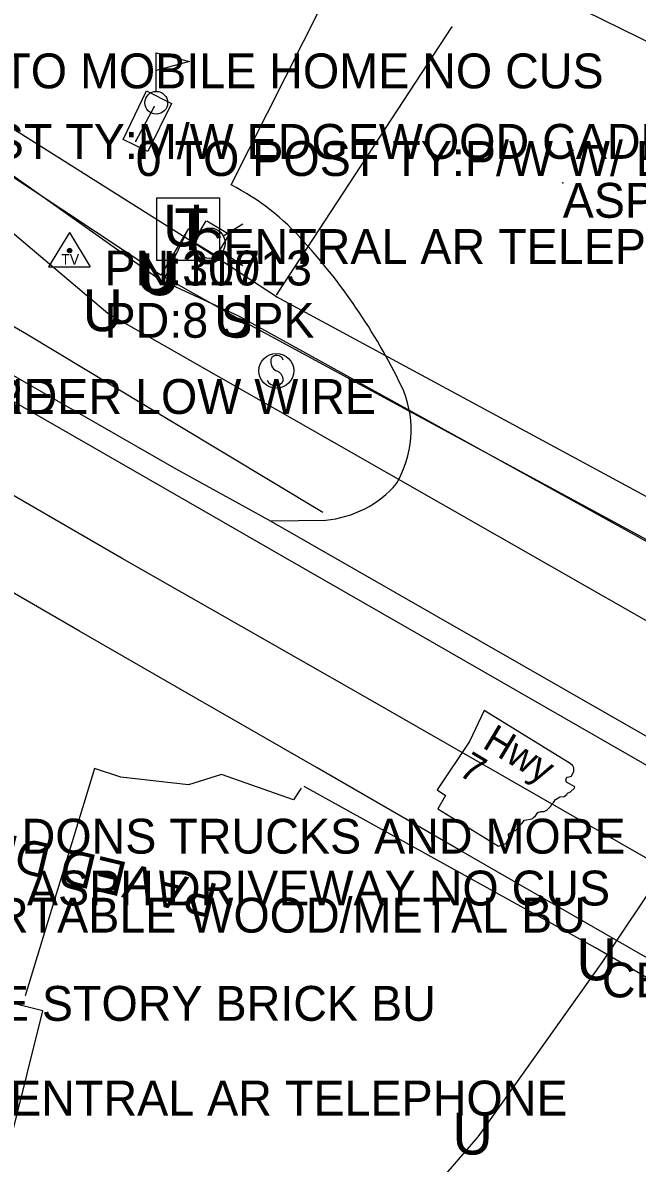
# Model space of a CAD drawing. Extents: x 954793 to 988390, y 1867850 to 1924428.
# Drawn here: x 967016.2 to 967104.3, y 1897074.8 to 1897238.3 of the extents above; entities that cross this region are included whole.
import ezdxf

# ---------------------------------------------------------------- set-up
doc = ezdxf.new("R2010")
doc.units = 0
for name, color, linetype in [('Default', 7, 'Continuous'), ('S_BUILDING', 7, 'Continuous'), ('S_DITCHLINE', 7, 'Continuous'), ('S_DRIVEWAY', 7, 'Continuous'), ('S_DRIVEWAY_ANNOT', 7, 'Continuous'), ('S_EDGE_CONCRETE', 7, 'Continuous'), ('S_EDGE_PAVEMENT', 7, 'Continuous'), ('S_ELECTRIC_UTILITIES_ANNOT', 7, 'Continuous'), ('S_FENCE', 7, 'Continuous'), ('S_FIBER_OPTIC_CABLE', 7, 'Continuous'), ('S_FLAG_POLE', 7, 'Continuous'), ('S_HWY_SYMBOLS', 7, 'Continuous'), ('S_MISC_TOPO_POINT', 7, 'Continuous'), ('S_MSC_PT_SYM', 7, 'Continuous'), ('S_PARKING', 7, 'Continuous'), ('S_PAVEMENT_CROWN', 7, 'Continuous'), ('S_SECONDARY_CTL', 7, 'Continuous'), ('S_SECONDARY_CTL_ANNOT', 7, 'Continuous'), ('S_SHOULDER', 7, 'Continuous'), ('S_SIGN', 7, 'Continuous'), ('S_SIGN_ANNOT', 7, 'Continuous'), ('S_SURVEY_TEXT_ANNOT', 7, 'Continuous'), ('S_TELEPHONE_UTILITIES', 7, 'Continuous'), ('S_TELEPHONE_UTILITIES_ANNOT', 7, 'Continuous'), ('S_UNDERGROUND_CABLE', 7, 'Continuous'), ('S_UNDERGROUND_CABLE_ANNOT', 7, 'Continuous'), ('S_UTL_PT_SYM', 7, 'Continuous'), ('S_WATER_UTILITIES', 7, 'Continuous')]:
    doc.layers.add(name, color=color, linetype=linetype)

msp = doc.modelspace()

# ---------------------------------------------------------------- linework, layer by layer
at = {"layer": 'S_BUILDING'}
for points in [[(967065.51, 1897255.42), (967081.45, 1897287.84), (967122.87, 1897267.47), (967129.83, 1897281.63), (967155.34, 1897269.09), (967148.3, 1897254.77), (967180.37, 1897239), (967164.5, 1897206.74)], [(967019.08, 1897096.61), (966964.64, 1897110.21), (966957.91, 1897083.3), (967012.36, 1897069.7)]]:
    msp.add_lwpolyline(points, close=True, dxfattribs=at)
at = {"layer": 'S_DITCHLINE'}
msp.add_lwpolyline([(967059.25, 1897168.09), (967038.01, 1897180.86), (967016.77, 1897193.64), (966999.71, 1897203.61), (966982.65, 1897213.58)], dxfattribs=at)
at = {"layer": 'S_DRIVEWAY'}
msp.add_lwpolyline([(967056.12, 1897128.53), (967055.04, 1897126.89), (967044.72, 1897130.5), (967039.98, 1897129.01), (967030.26, 1897130.1), (967026.52, 1897131.35), (967021.55, 1897115.05), (967016.59, 1897098.75)], dxfattribs=at)
at = {"layer": 'S_EDGE_CONCRETE'}
msp.add_lwpolyline([(967030.61, 1897221.59), (967033.97, 1897228.53), (967037.54, 1897226.74), (967034.14, 1897219.87)], close=True, dxfattribs=at)
at = {"layer": 'S_EDGE_PAVEMENT'}
for points in [[(967224.91, 1897063.58), (967209.92, 1897072.14), (967194.93, 1897080.7), (967179.94, 1897089.26), (967164.94, 1897097.82), (967149.95, 1897106.38), (967130.9, 1897117.31), (967111.86, 1897128.24), (967091.31, 1897140.05), (967070.75, 1897151.86), (967053.62, 1897161.71), (967036.49, 1897171.56), (967019.54, 1897181.3), (967002.59, 1897191.04), (966985.41, 1897201.15), (966968.24, 1897211.26), (966949.08, 1897223.02), (966929.92, 1897234.79), (966913.05, 1897245.66), (966896.19, 1897256.54), (966878.48, 1897268.84), (966872.08, 1897273.28)], [(967228.06, 1897034.22), (967213.07, 1897042.79), (967198.07, 1897051.35), (967183.07, 1897059.92), (967168.07, 1897068.49), (967153.07, 1897077.06), (967138.08, 1897085.63), (967118.85, 1897096.66), (967099.63, 1897107.69), (967079.02, 1897119.57), (967058.4, 1897131.45), (967041.37, 1897141.26), (967024.35, 1897151.07), (967007.47, 1897160.83), (966990.59, 1897170.6), (966973.37, 1897180.77), (966956.14, 1897190.94), (966936.51, 1897202.73), (966916.87, 1897214.51), (966899.69, 1897225.68), (966882.51, 1897236.85), (966864.51, 1897249.13)]]:
    msp.add_lwpolyline(points, dxfattribs=at)
at = {"layer": 'S_FENCE'}
msp.add_lwpolyline([(967042.6, 1897209.93), (967045.82, 1897208), (967043.93, 1897204.89), (967040.72, 1897206.84), (967042.49, 1897209.89)], dxfattribs=at)
at = {"layer": 'S_FIBER_OPTIC_CABLE'}
for p, q in [((967035.71, 1897201.53), (967003.19, 1897224.63)), ((967047.27, 1897196.19), (967035.71, 1897201.53)), ((967126.15, 1897152.57), (967047.27, 1897196.19))]:
    msp.add_line(p, q, dxfattribs=at)
at = {"layer": 'S_FLAG_POLE'}
for p, q in [((967035.36, 1897228.48), (967035.36, 1897234.02)), ((967035.36, 1897234.02), (967040.12, 1897232.74)), ((967040.12, 1897232.74), (967035.36, 1897231.47))]:
    msp.add_line(p, q, dxfattribs=at)
msp.add_circle((967035.36, 1897226.85), 1.63, dxfattribs=at)
at = {"layer": 'S_HWY_SYMBOLS'}
msp.add_lwpolyline([(967082.36, 1897139.67), (967080.26, 1897135.22), (967075.61, 1897128.32), (967076.8, 1897127.5), (967075.74, 1897125.57), (967084.41, 1897120.25), (967085.5, 1897120.59), (967085.91, 1897121.43), (967085.84, 1897121.97), (967086.45, 1897122.49), (967086.83, 1897122.46), (967087.12, 1897122.78), (967087.29, 1897123.07), (967087.75, 1897123.49), (967088.12, 1897123.96), (967089.24, 1897124.17), (967089.45, 1897124.35), (967089.7, 1897124.6), (967090.07, 1897125.06), (967090.54, 1897125.18), (967090.96, 1897125.22), (967091.35, 1897125.38), (967091.6, 1897125.63), (967091.89, 1897125.94), (967092.07, 1897126.23), (967092.32, 1897126.48), (967092.58, 1897126.92), (967092.69, 1897126.95), (967093.06, 1897127.22), (967093.22, 1897127.32), (967093.83, 1897127.35), (967094.19, 1897127.63), (967094.32, 1897127.85), (967094.72, 1897128.01), (967095.33, 1897128.53), (967095.34, 1897128.72), (967094.18, 1897129.42), (967094.05, 1897129.69), (967094.2, 1897130.1), (967094.54, 1897130.19), (967094.89, 1897130.27), (967095.21, 1897130.97), (967095.22, 1897131.47), (967095.08, 1897131.74), (967094.69, 1897132.08), (967082.36, 1897139.67)], dxfattribs=at)
at = {"layer": 'S_MSC_PT_SYM'}
for points in [[(967035.04, 1897226.28), (967035.04, 1897226.33), (967035.04, 1897226.28), (967034.99, 1897226.28), (967035.04, 1897226.28), (967035.04, 1897226.23), (967035.04, 1897226.28), (967035.09, 1897226.28)], [(967032.41, 1897221.34), (967032.41, 1897221.39), (967032.41, 1897221.34), (967032.36, 1897221.34), (967032.41, 1897221.34), (967032.41, 1897221.29), (967032.41, 1897221.34), (967032.46, 1897221.34)], [(967093.62, 1897215.35), (967093.62, 1897215.4), (967093.62, 1897215.35), (967093.57, 1897215.35), (967093.62, 1897215.35), (967093.62, 1897215.3), (967093.62, 1897215.35), (967093.67, 1897215.35)], [(967016.82, 1897116.72), (967016.82, 1897116.77), (967016.82, 1897116.72), (967016.77, 1897116.72), (967016.82, 1897116.72), (967016.82, 1897116.67), (967016.82, 1897116.72), (967016.87, 1897116.72)]]:
    msp.add_lwpolyline(points, dxfattribs=at)
at = {"layer": 'S_PARKING'}
for points in [[(967046.08, 1897215.07), (967064.23, 1897251.14), (967082.58, 1897241.92), (967086.54, 1897249.56)], [(967051.83, 1897166.87), (967059.66, 1897166.99)]]:
    msp.add_lwpolyline(points, dxfattribs=at)
for centre, major_axis, ratio, start_param, end_param in [((967030.19, 1897184.38), (-34.3, 6.15), 0.990938, 4.031216, 4.414458), ((966993.04, 1897148.79), (26.98, 81.77), 0.998092, 5.470715, 5.771687), ((967056.82, 1897179.88), (7.86, 12.92), 0.99535, 4.725896, 5.636188), ((967058.37, 1897181.85), (14.35, 4.39), 0.993652, 4.503397, 5.283382)]:
    msp.add_ellipse(centre, major_axis=major_axis, ratio=ratio, start_param=start_param, end_param=end_param, dxfattribs=at)
at = {"layer": 'S_PAVEMENT_CROWN'}
msp.add_lwpolyline([(967219.07, 1897053.37), (967204.08, 1897061.93), (967189.09, 1897070.5), (967174.1, 1897079.07), (967159.1, 1897087.64), (967144.11, 1897096.21), (967124.99, 1897107.29), (967105.86, 1897118.37), (967085.28, 1897130.17), (967064.7, 1897141.97), (967047.59, 1897151.73), (967030.48, 1897161.48), (967013.54, 1897171.29), (966996.59, 1897181.09), (966979.32, 1897191.11), (966962.05, 1897201.13), (966942.6, 1897212.9), (966923.16, 1897224.68), (966906.14, 1897235.69), (966889.12, 1897246.7), (966871.33, 1897259.04), (966853.54, 1897271.38)], dxfattribs=at)
at = {"layer": 'S_SECONDARY_CTL'}
for p, q in [((967022.94, 1897208.25), (967019.93, 1897203.3)), ((967022.94, 1897208.25), (967025.89, 1897203.3)), ((967019.93, 1897203.3), (967025.89, 1897203.3))]:
    msp.add_line(p, q, dxfattribs=at)
for radius in [0.311, 0.183, 0.103]:
    msp.add_circle((967022.94, 1897205.64), radius, dxfattribs=at)
at = {"layer": 'S_SHOULDER'}
for points in [[(967232.64, 1897063.32), (967214.53, 1897073.69), (967196.41, 1897084.05), (967178.29, 1897094.41), (967160.18, 1897104.78), (967142.06, 1897115.14), (967123.94, 1897125.5), (967105.83, 1897135.87), (967087.71, 1897146.23), (967069.6, 1897156.59), (967051.48, 1897166.96), (967038.32, 1897174.25), (967021.18, 1897184.1), (967004.04, 1897193.95), (966987.03, 1897204.08), (966970.01, 1897214.2), (966950.65, 1897225.8), (966931.29, 1897237.39), (966914.48, 1897248.11), (966897.67, 1897258.82), (966879.98, 1897271.02), (966862.29, 1897283.22)], [(967406.8, 1896929.13), (967391.8, 1896937.69), (967376.8, 1896946.26), (967361.8, 1896954.82), (967346.8, 1896963.39), (967331.8, 1896971.95), (967316.8, 1896980.52), (967301.8, 1896989.08), (967286.8, 1896997.64), (967271.8, 1897006.21), (967256.8, 1897014.77), (967241.8, 1897023.34), (967226.8, 1897031.9), (967211.8, 1897040.47), (967196.8, 1897049.03), (967181.8, 1897057.6), (967166.8, 1897066.16), (967151.8, 1897074.73), (967136.8, 1897083.29), (967117.55, 1897094.47), (967098.3, 1897105.65), (967077.43, 1897117.22), (967056.55, 1897128.79)]]:
    msp.add_lwpolyline(points, dxfattribs=at)
at = {"layer": 'S_SIGN'}
msp.add_line((967032.41, 1897221.34), (967035.04, 1897226.28), dxfattribs=at)
msp.add_circle((967052.57, 1897188.4), 2.49, dxfattribs=at)
for centre, radius, start, end in [((967052.65, 1897189.67), 0.95, 16.5258, 156.8957), ((967053.26, 1897189.73), 1.5, 167.1196, 241.9813), ((967052.42, 1897187.58), 1.28, 204.641, 335.359), ((967052.16, 1897187.06), 1.4, 358.6529, 73.7063)]:
    msp.add_arc(centre, radius, start, end, dxfattribs=at)
at = {"layer": 'S_TELEPHONE_UTILITIES'}
msp.add_lwpolyline([(967035.42, 1897204.2), (967035.42, 1897213.2), (967044.42, 1897213.2), (967044.42, 1897204.2)], close=True, dxfattribs=at)
at = {"layer": 'S_UNDERGROUND_CABLE'}
for p, q in [((967036.03, 1897202.13), (967002.89, 1897224.09)), ((967028.43, 1897196.63), (967003.94, 1897217.33)), ((967039.96, 1897208.8), (967036.03, 1897202.13)), ((967036.62, 1897201.77), (967039.96, 1897208.8)), ((967047.23, 1897195.8), (967036.62, 1897201.77)), ((967116.81, 1897146.16), (967028.43, 1897196.63)), ((967126.33, 1897152.93), (967047.23, 1897195.8)), ((967115.4, 1897127.72), (967099.22, 1897103.54)), ((967099.22, 1897103.54), (967081.44, 1897078.54)), ((967081.44, 1897078.54), (967057.23, 1897050.51))]:
    msp.add_line(p, q, dxfattribs=at)
at = {"layer": 'S_UTL_PT_SYM'}
for points in [[(967077.74, 1897237.69), (967077.74, 1897237.74), (967077.74, 1897237.69), (967077.69, 1897237.69), (967077.74, 1897237.69), (967077.74, 1897237.64), (967077.74, 1897237.69), (967077.79, 1897237.69)], [(967042.24, 1897205.79), (967042.24, 1897205.84), (967042.24, 1897205.79), (967042.19, 1897205.79), (967042.24, 1897205.79), (967042.24, 1897205.74), (967042.24, 1897205.79), (967042.29, 1897205.79)], [(967035.71, 1897201.53), (967035.71, 1897201.58), (967035.71, 1897201.53), (967035.66, 1897201.53), (967035.71, 1897201.53), (967035.71, 1897201.48), (967035.71, 1897201.53), (967035.76, 1897201.53)], [(967052.61, 1897199.01), (967052.61, 1897199.06), (967052.61, 1897199.01), (967052.56, 1897199.01), (967052.61, 1897199.01), (967052.61, 1897198.96), (967052.61, 1897199.01), (967052.66, 1897199.01)], [(967052.63, 1897199.34), (967052.63, 1897199.39), (967052.63, 1897199.34), (967052.58, 1897199.34), (967052.63, 1897199.34), (967052.63, 1897199.29), (967052.63, 1897199.34), (967052.68, 1897199.34)], [(967047.27, 1897196.19), (967047.27, 1897196.24), (967047.27, 1897196.19), (967047.22, 1897196.19), (967047.27, 1897196.19), (967047.27, 1897196.14), (967047.27, 1897196.19), (967047.32, 1897196.19)]]:
    msp.add_lwpolyline(points, dxfattribs=at)
at = {"layer": 'S_WATER_UTILITIES'}
for p, q in [((967052.63, 1897199.34), (967077.74, 1897237.69)), ((967042.24, 1897205.79), (967002.71, 1897230.69)), ((967044.96, 1897207.75), (967047.78, 1897209.49)), ((967052.61, 1897199.01), (967042.24, 1897205.79)), ((967044.84, 1897205.44), (967047.75, 1897203.52)), ((967130.07, 1897157.11), (967052.61, 1897199.01))]:
    msp.add_line(p, q, dxfattribs=at)
msp.add_circle((967043.06, 1897206.7), 2.18, dxfattribs=at)

# ---------------------------------------------------------------- texts
at = {"layer": 'Default'}
for p in [(967036.33, 1897206.25), (967032.4, 1897199.58), (967032.99, 1897199.23), (967024.8, 1897194.08), (967043.6, 1897193.25), (967095.59, 1897100.99), (967077.81, 1897076)]:
    msp.add_text('U', height=6, rotation=360, dxfattribs=at).set_placement(p)
at = {"layer": 'S_DRIVEWAY_ANNOT'}
msp.add_text('PAVED DRIVE', height=5.0004, rotation=166.5819, dxfattribs=at).set_placement((967044.44, 1897114.72))
at = {"layer": 'S_ELECTRIC_UTILITIES_ANNOT'}
msp.add_text('LOW WIRE', height=5, dxfattribs=at).set_placement((966986.26, 1897182.22))
at = {"layer": 'S_HWY_SYMBOLS'}
for s, p in [('Hwy', (967081.95, 1897134.44)), ('7', (967078.49, 1897130.53))]:
    msp.add_text(s, height=4, rotation=328.9645, dxfattribs=at).set_placement(p)
at = {"layer": 'S_MISC_TOPO_POINT'}
msp.add_text('SHOT UNDER LOW WIRE', height=5, dxfattribs=at).set_placement((966986.26, 1897182.22))
at = {"layer": 'S_SECONDARY_CTL'}
msp.add_text('TV', height=1.5, rotation=360, dxfattribs=at).set_placement((967021.74, 1897203.63))
at = {"layer": 'S_SECONDARY_CTL_ANNOT'}
for s, p in [('PN:30013', (967027.94, 1897200.64)), ('PN:1171', (967027.94, 1897200.64)), ('PD:8 SPK', (967027.94, 1897193.14)), ('PD:8 SPK', (967027.94, 1897193.14))]:
    msp.add_text(s, height=5, dxfattribs=at).set_placement(p)
at = {"layer": 'S_SIGN_ANNOT'}
for s, p in [('0 TO POST TY:M/W EDGEWOOD CADDO DRIVE', (966985.54, 1897218.8)), ('0 TO POST TY:P/W W/ ELEC. PERMIT', (967032.41, 1897216.34)), ('0 TO POST TY:M DONS TRUCKS AND MORE', (966961.45, 1897119.16))]:
    msp.add_text(s, height=5, dxfattribs=at).set_placement(p)
at = {"layer": 'S_SURVEY_TEXT_ANNOT'}
for s, p in [('GRAVEL DW TO MOBILE HOME NO CUS', (966971.31, 1897228.91)), ('ASPH PARKNG', (967093.62, 1897210.35)), ('ASPH DRIVEWAY NO CUS', (967016.82, 1897111.72)), ('PORTABLE WOOD/METAL BU', (967002.58, 1897107.83)), ('ONE STORY BRICK BU', (967002.62, 1897095.18))]:
    msp.add_text(s, height=5, dxfattribs=at).set_placement(p)
at = {"layer": 'S_TELEPHONE_UTILITIES'}
msp.add_text('T', height=6, rotation=360, dxfattribs=at).set_placement((967037.98, 1897205.7))
at = {"layer": 'S_TELEPHONE_UTILITIES_ANNOT'}
msp.add_text('CENTRAL AR TELEPHONE', height=5, dxfattribs=at).set_placement((967040.15, 1897203.72))
at = {"layer": 'S_UNDERGROUND_CABLE_ANNOT'}
for s, p in [('CENTRAL AR TELEPHONE', (967099.22, 1897098.54)), ('TY:TELEPHONE CENTRAL AR TELEPHONE', (966956.83, 1897081.6))]:
    msp.add_text(s, height=5, dxfattribs=at).set_placement(p)

doc.saveas('drawing.dxf')
